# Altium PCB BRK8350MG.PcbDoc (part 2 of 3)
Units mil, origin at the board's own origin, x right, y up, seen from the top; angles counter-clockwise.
Board outline 8858.27 x 5511.81 mil, 6 copper layers (L1-TOP, L2-GND, L3-PWR, L4-PWR, L5-GND, L6-BOT), stack 81.526 mil thick; 49 components, 350 nets, 1087 pads, 250 vias.
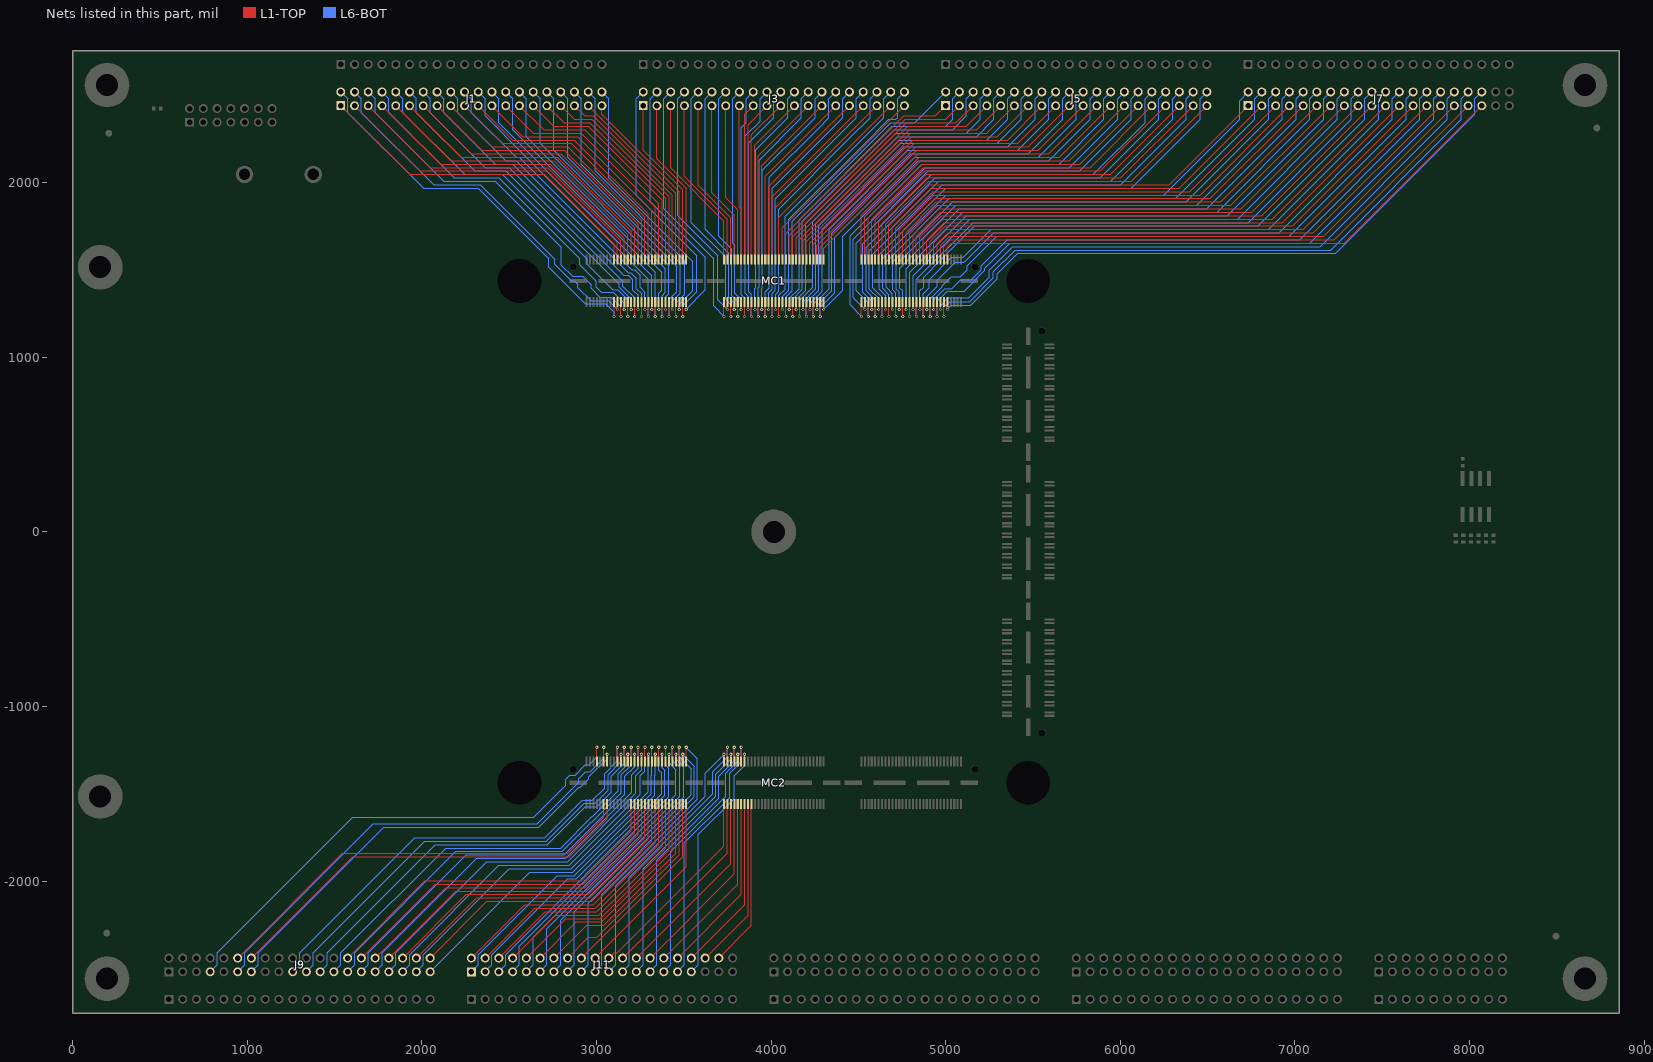
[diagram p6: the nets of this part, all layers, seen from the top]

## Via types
v1: diameter 18, hole 10, L1-TOP to L6-BOT, tented both sides, 250 vias

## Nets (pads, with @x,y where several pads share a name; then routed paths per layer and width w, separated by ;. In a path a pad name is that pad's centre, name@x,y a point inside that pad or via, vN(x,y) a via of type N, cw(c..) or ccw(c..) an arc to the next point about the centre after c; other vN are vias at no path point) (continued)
B44_L7P: J9.7 MC2.7 | length 2919.7
  L1-TOP w5: MC2.7@3001.98,-1313.34 v1(3001.98,-1233.34)
  L6-BOT w5: J9.7@787.4,-2519.69 826.77,-2480.32 826.77,-2411.42 1604.33,-1633.86 2640.14,-1633.86 2824,-1450 2824,-1415.82 2846.82,-1393 2878.98,-1393 2937.03,-1334.95 2958.3,-1334.95 3001.98,-1291.27 v1@3001.98,-1235.34
B44_L8N: J9.14 MC2.14 | length 2452.7
  L1-TOP w5: J9.14@1023.62,-2440.94 1604.33,-1860.24 2844.49,-1860.24 3061.04,-1643.68 MC2.14@3061.04,-1558.65
B44_L8P: J9.12 MC2.12 | length 2506
  L1-TOP w5: J9.12@944.88,-2440.94 1545.28,-1840.55 2834.65,-1840.55 3041.35,-1633.84 MC2.12@3041.35,-1558.65
B44_L9N: J9.13 MC2.13 | length 2655.6
  L1-TOP w5: MC2.13@3061.04,-1313.34 v1(3061.04,-1273.34)
  L6-BOT w5: J9.13@1023.62,-2519.69 1062.99,-2480.32 1062.99,-2411.42 1781.65,-1692.76 2668.42,-1692.76 2898.17,-1463 2908.21,-1463 2956.18,-1415.03 2956.18,-1403.3 3061.04,-1298.44 v1(3061.04,-1273.34)
B44_L9P: J9.11 MC2.11 | length 2796.8
  L1-TOP w5: MC2.11@3041.35,-1313.34 v1(3041.35,-1233.34)
  L6-BOT w5: J9.11@944.88,-2519.69 984.25,-2480.32 984.25,-2411.42 1722.44,-1673.23 2660.35,-1673.23 2899,-1434.57 2899,-1415 2939.97,-1374.03 2964.99,-1374.03 3041.35,-1297.67 v1@3041.35,-1235.34
B44_L10N: J9.21 MC2.21 | length 2474.4
  L1-TOP w5: MC2.21@3139.78,-1313.34 v1(3139.78,-1273.34)
  L6-BOT w5: J9.21@1338.58,-2519.69 1377.95,-2480.32 1377.95,-2411.42 2017.72,-1771.65 2712.35,-1771.65 2931,-1553 2994.24,-1553 3066.05,-1481.19 3066.05,-1390.95 3139.78,-1317.22 v1@3139.78,-1275.34
B44_L10P: J9.19 MC2.19 | length 2605.2
  L1-TOP w5: MC2.19@3120.09,-1313.34 v1(3120.09,-1233.34)
  L6-BOT w5: J9.19@1259.84,-2519.69 1299.21,-2480.32 1299.21,-2411.42 1958.66,-1751.97 2703.03,-1751.97 2918,-1537 2976.57,-1537 3046.03,-1467.54 3046.03,-1385.97 3120.09,-1311.91 v1@3120.09,-1235.34
B45_L1N: J11.12 MC2.52 | length 1282.7
  L1-TOP w5: J11.12@2677.17,-2440.94 2883.86,-2234.25 3031.5,-2234.25 3435.06,-1830.69 MC2.52@3435.06,-1558.65
B45_L1P: J11.10 MC2.50 | length 1336
  L1-TOP w5: J11.10@2598.43,-2440.94 2824.8,-2214.57 3021.65,-2214.57 3415.37,-1820.85 MC2.50@3415.37,-1558.65
B45_L2N: J11.4 MC2.44 | length 1495.9
  L1-TOP w5: J11.4@2362.2,-2440.94 2647.64,-2155.51 2992.13,-2155.51 3356.31,-1791.32 MC2.44@3356.31,-1558.65
B45_L2P: J11.2 MC2.42 | length 1549.2
  L1-TOP w5: J11.2@2283.46,-2440.94 2588.58,-2135.83 2982.28,-2135.83 3336.63,-1781.48 MC2.42@3336.63,-1558.65
B45_L3N: J11.38 MC2.78 | length 959.8
  L1-TOP w5: J11.38@3700.79,-2440.94 3887.81,-2253.92 MC2.78@3887.81,-1558.65
B45_L3P: J11.36 MC2.76 | length 984.2
  L1-TOP w5: J11.36@3622.05,-2440.94 3868.13,-2194.87 MC2.76@3868.13,-1558.65
B45_L4N: J11.29 MC2.69 | length 1459.7
  L1-TOP w5: MC2.69@3809.07,-1313.34 v1(3809.07,-1273.34)
  L6-BOT w5: J11.29@3385.83,-2519.69 3425.2,-2480.31 3425.2,-1830.71 3740.61,-1515.29 3740.61,-1382.39 3809.07,-1313.93 v1@3809.07,-1275.34
B45_L4P: J11.27 MC2.67 | length 1564.1
  L1-TOP w5: MC2.67@3789.39,-1313.34 v1(3789.39,-1233.34)
  L6-BOT w5: J11.27@3307.09,-2519.69 3346.46,-2480.31 3346.46,-1879.92 3700,-1526.38 3700,-1399 3789.39,-1309.61 v1@3789.39,-1235.34
B45_L5N: J11.20 MC2.60 | length 1098.4
  L1-TOP w5: J11.20@2992.13,-2440.94 3041.34,-2391.73 3513.8,-1919.28 MC2.60@3513.8,-1558.65
B45_L5P: J11.18 MC2.58 | length 1122.8
  L1-TOP w5: J11.18@2913.39,-2440.94 2982.28,-2372.05 3494.11,-1860.22 MC2.58@3494.11,-1558.65
B45_L6N: J9.40 MC2.40 | length 1759.9
  L1-TOP w5: J9.40@2047.24,-2440.95 2372.05,-2116.14 2972.44,-2116.14 3316.94,-1771.64 MC2.40@3316.94,-1558.65
B45_L6P: J9.38 MC2.38 | length 1813.2
  L1-TOP w5: J9.38@1968.5,-2440.95 2312.99,-2096.46 2962.6,-2096.46 3297.26,-1761.8 MC2.38@3297.26,-1558.65
B45_L7N: J11.8 MC2.48 | length 1389.3
  L1-TOP w5: J11.8@2519.68,-2440.94 2765.75,-2194.88 3011.81,-2194.88 3395.69,-1811.01 MC2.48@3395.69,-1558.65
B45_L7P: J11.6 MC2.46 | length 1442.6
  L1-TOP w5: J11.6@2440.94,-2440.94 2706.69,-2175.2 3001.97,-2175.2 3376,-1801.17 MC2.46@3376,-1558.65
B45_L8N: J11.19 MC2.59 | length 1633.6
  L1-TOP w5: MC2.59@3513.8,-1313.34 v1(3513.8,-1233.34)
  L6-BOT w5: J11.19@2992.13,-2519.69 3031.5,-2480.31 3031.5,-2077.5 3578,-1531 3578,-1299.54 v1@3513.8,-1235.34
B45_L8P: J11.17 MC2.57 | length 1580.6
  L1-TOP w5: MC2.57@3494.11,-1313.34 v1(3494.11,-1273.34)
  L6-BOT w5: J11.17@2913.39,-2519.69 2952.76,-2480.31 2952.76,-2125.98 3561.31,-1517.43 3561.31,-1342.54 v1@3494.11,-1275.34
B45_L9N: J11.24 MC2.64 | length 1131
  L1-TOP w5: J11.24@3149.61,-2440.94 3750.02,-1840.54 MC2.64@3750.02,-1558.65
B45_L9P: J11.22 MC2.62 | length 1167
  L1-TOP w5: J11.22@3070.87,-2440.94 3100.39,-2411.42 3120.08,-2411.42 3730.33,-1801.17 MC2.62@3730.33,-1558.65
B45_L10N: J11.15 MC2.55 | length 1687.1
  L1-TOP w5: MC2.55@3474.43,-1313.34 v1(3474.43,-1233.34)
  L6-BOT w5: J11.15@2834.65,-2519.69 2874.02,-2480.32 2874.02,-2175.2 3544.18,-1505.03 3544.18,-1357.18 3474.43,-1287.43 v1@3474.43,-1235.34
B45_L10P: J11.13 MC2.53 | length 1612.1
  L1-TOP w5: MC2.53@3454.74,-1313.34 v1(3454.74,-1273.34)
  L6-BOT w5: J11.13@2755.91,-2519.69 2795.28,-2480.31 2795.28,-2224.41 3501,-1518.68 3501,-1345 3454.74,-1298.74 v1@3454.74,-1275.34
B45_L11N: J11.33 MC2.73 | length 1410.7
  L1-TOP w5: MC2.73@3848.44,-1313.34 v1(3848.44,-1273.34)
  L6-BOT w5: J11.33@3543.31,-2519.69 3582.68,-2480.31 3582.68,-1732.28 3787.72,-1527.24 3787.72,-1396.28 3848.44,-1335.56 v1@3848.44,-1275.34
B45_L11P: J11.31 MC2.71 | length 1515.2
  L1-TOP w5: MC2.71@3828.76,-1313.34 v1(3828.76,-1233.34)
  L6-BOT w5: J11.31@3464.57,-2519.69 3503.94,-2480.31 3503.94,-1781.5 3763.57,-1521.86 3763.57,-1381.43 3828.76,-1316.24 v1@3828.76,-1235.34
B45_L12N: J11.7 MC2.47 | length 1741.5
  L1-TOP w5: MC2.47@3395.69,-1313.34 v1(3395.69,-1233.34)
  L6-BOT w5: J11.7@2519.68,-2519.69 2559.06,-2480.32 2559.06,-2372.05 3413,-1518.1 3413,-1353 3395.69,-1335.69 v1@3395.69,-1235.34
B45_L12P: J11.5 MC2.45 | length 1684.9
  L1-TOP w5: MC2.45@3376,-1313.34 v1(3376,-1273.34)
  L6-BOT w5: J11.5@2440.94,-2519.69 2480.32,-2480.31 2480.32,-2421.26 3392,-1509.57 3392,-1366 3376,-1350 v1@3376,-1275.34
B45_L13N: J11.34 MC2.74 | length 1008.7
  L1-TOP w5: J11.34@3543.31,-2440.94 3848.44,-2135.81 MC2.74@3848.44,-1558.65
B45_L13P: J11.32 MC2.72 | length 1033.2
  L1-TOP w5: J11.32@3464.57,-2440.94 3828.76,-2076.76 MC2.72@3828.76,-1558.65
B45_L14N: J11.30 MC2.70 | length 1057.6
  L1-TOP w5: J11.30@3385.83,-2440.94 3809.07,-2017.7 MC2.70@3809.07,-1558.65
B45_L14P: J11.28 MC2.68 | length 1082.1
  L1-TOP w5: J11.28@3307.09,-2440.94 3789.39,-1958.65 MC2.68@3789.39,-1558.65
B45_L15N: J9.34 MC2.34 | length 1919.8
  L1-TOP w5: J9.34@1811.02,-2440.95 2194.88,-2057.09 2942.91,-2057.09 3257.89,-1742.11 MC2.34@3257.89,-1558.65
B45_L15P: J9.32 MC2.32 | length 1973.1
  L1-TOP w5: J9.32@1732.28,-2440.95 2135.83,-2037.4 2933.07,-2037.4 3238.2,-1732.27 MC2.32@3238.2,-1558.65
B45_L16N: J11.23 MC2.63 | length 1613
  L1-TOP w5: MC2.63@3750.02,-1313.34 v1(3750.02,-1233.34)
  L6-BOT w5: J11.23@3149.61,-2519.69 3188.98,-2480.31 3188.98,-1978.35 3666,-1501.32 3666,-1374 3750.02,-1289.98 v1@3750.02,-1235.34
B45_L16P: J11.21 MC2.61 | length 1557.5
  L1-TOP w5: MC2.61@3730.33,-1313.34 v1(3730.33,-1273.34)
  L6-BOT w5: J11.21@3070.87,-2519.69 3110.24,-2480.31 3110.24,-2027.56 3622.27,-1515.52 3622.27,-1383.4 v1@3730.33,-1275.34
B45_L17N: J11.16 MC2.56 | length 1176.1
  L1-TOP w5: J11.16@2834.65,-2440.94 2952.76,-2322.83 3001.97,-2322.83 3474.43,-1850.38 MC2.56@3474.43,-1558.65
B45_L17P: J11.14 MC2.54 | length 1229.4
  L1-TOP w5: J11.14@2755.91,-2440.94 2942.91,-2253.94 3041.34,-2253.94 3454.74,-1840.54 MC2.54@3454.74,-1558.65
B45_L18N: J9.33 MC2.33 | length 2154.6
  L1-TOP w5: MC2.33@3257.89,-1313.34 v1(3257.89,-1273.34)
  L6-BOT w5: J9.33@1811.02,-2519.69 1850.39,-2480.32 1850.39,-2411.42 2372.05,-1889.76 2834.65,-1889.76 3226,-1498.41 3226,-1395.78 3257.89,-1363.89 v1@3257.89,-1275.34
B45_L18P: J9.31 MC2.31 | length 2287.9
  L1-TOP w5: MC2.31@3238.2,-1313.34 v1(3238.2,-1233.34)
  L6-BOT w5: J9.31@1732.28,-2519.69 1771.65,-2480.32 1771.65,-2411.42 2312.99,-1870.08 2824.8,-1870.08 3202.94,-1491.94 3202.94,-1390.03 3238.2,-1354.77 v1@3238.2,-1235.34
B45_L19N: J11.11 MC2.51 | length 1713
  L1-TOP w5: MC2.51@3435.06,-1313.34 v1(3435.06,-1233.34)
  L6-BOT w5: J11.11@2677.17,-2519.69 2716.54,-2480.32 2716.54,-2273.62 3477,-1513.16 3477,-1349 3435.06,-1307.06 v1@3435.06,-1235.34
B45_L19P: J11.9 MC2.49 | length 1655.6
  L1-TOP w5: MC2.49@3415.37,-1313.34 v1(3415.37,-1273.34)
  L6-BOT w5: J11.9@2598.43,-2519.69 2637.8,-2480.31 2637.8,-2322.83 3455,-1505.63 3455,-1362 3415.37,-1322.37 v1@3415.37,-1275.34
B45_L20N: J9.29 MC2.29 | length 2261.2
  L1-TOP w5: MC2.29@3218.52,-1313.34 v1(3218.52,-1273.34)
  L6-BOT w5: J9.29@1653.54,-2519.69 1692.91,-2480.32 1692.91,-2411.42 2253.94,-1850.39 2814.96,-1850.39 3162.31,-1503.04 3162.31,-1400.6 3218.52,-1344.39 v1@3218.52,-1275.34
B45_L20P: J9.27 MC2.27 | length 2394.5
  L1-TOP w5: MC2.27@3198.83,-1313.34 v1(3198.83,-1233.34)
  L6-BOT w5: J9.27@1574.8,-2519.69 1614.17,-2480.32 1614.17,-2411.42 2194.88,-1830.71 2805.12,-1830.71 3142.2,-1493.63 3142.2,-1392.43 3198.83,-1335.79 v1@3198.83,-1235.34
B45_L21N: J11.3 MC2.43 | length 1819.1
  L1-TOP w5: MC2.43@3356.32,-1313.34 v1(3356.32,-1233.34)
  L6-BOT w5: J11.3@2362.2,-2519.69 2401.57,-2480.32 2401.57,-2421.26 2834.65,-1988.19 2883.86,-1988.19 3373.39,-1498.66 3373.39,-1381.07 3356.32,-1364 v1@3356.32,-1235.34
B45_L21P: J11.1 MC2.41 | length 1778.2
  L1-TOP w5: MC2.41@3336.63,-1313.34 v1(3336.63,-1273.34)
  L6-BOT w5: J11.1@2283.46,-2519.69 2322.83,-2480.32 2322.83,-2421.26 2775.59,-1968.5 2874.02,-1968.5 3333.87,-1508.65 3333.87,-1395.05 3336.63,-1392.29 v1@3336.63,-1275.34
B45_L22N: J9.25 MC2.25 | length 2368.1
  L1-TOP w5: MC2.25@3179.15,-1313.34 v1(3179.15,-1273.34)
  L6-BOT w5: J9.25@1496.06,-2519.69 1535.43,-2480.32 1535.43,-2411.42 2135.83,-1811.02 2795.28,-1811.02 2977.15,-1629.15 2977.65,-1629.15 2993.18,-1613.62 2993.18,-1613.12 3123.64,-1482.66 3123.64,-1385.89 3179.15,-1330.39 v1@3179.15,-1275.34
B45_L22P: J9.23 MC2.23 | length 2501.1
  L1-TOP w5: MC2.23@3159.46,-1313.34 v1(3159.46,-1233.34)
  L6-BOT w5: J9.23@1417.32,-2519.69 1456.69,-2480.32 1456.69,-2411.42 2076.77,-1791.34 2719.34,-1791.34 2935.68,-1575 3001.77,-1575 3084.1,-1492.67 3084.1,-1399.67 3159.46,-1324.3 v1@3159.46,-1235.34
B45_L23N: J9.30 MC2.30 | length 2026.4
  L1-TOP w5: J9.30@1653.54,-2440.95 2076.77,-2017.72 2923.23,-2017.72 3218.52,-1722.43 MC2.30@3218.52,-1558.65
B45_L23P: J9.28 MC2.28 | length 2079.7
  L1-TOP w5: J9.28@1574.8,-2440.95 2017.72,-1998.03 2913.39,-1998.03 3198.83,-1712.58 MC2.28@3198.83,-1558.65
B45_L24N: J9.39 MC2.39 | length 2034.4
  L1-TOP w5: MC2.39@3316.94,-1313.34 v1(3316.94,-1233.34)
  L6-BOT w5: J9.39@2047.24,-2519.69 2618.11,-1948.82 2864.17,-1948.82 3314,-1498.99 3314,-1397 3316.94,-1394.06 v1@3316.94,-1235.34
B45_L24P: J9.37 MC2.37 | length 2042.3
  L1-TOP w5: MC2.37@3297.26,-1313.34 v1(3297.26,-1273.34)
  L6-BOT w5: J9.37@1968.5,-2519.69 2007.87,-2480.32 2007.87,-2421.26 2500,-1929.13 2854.33,-1929.13 3295.22,-1488.25 3295.22,-1397.04 3297.26,-1395 v1@3297.26,-1275.34
B45_T0U_N12: J9.36 MC2.36 | length 1866.5
  L1-TOP w5: J9.36@1889.76,-2440.95 2253.94,-2076.77 2952.76,-2076.77 3277.57,-1751.95 MC2.36@3277.57,-1558.65
B45_T1U_N12: J9.35 MC2.35 | length 2175.6
  L1-TOP w5: MC2.35@3277.57,-1313.34 v1(3277.57,-1233.34)
  L6-BOT w5: J9.35@1889.76,-2519.69 1929.13,-2480.32 1929.13,-2421.26 2440.94,-1909.45 2844.49,-1909.45 3251,-1502.94 3251,-1396.3 3277.57,-1369.72 v1@3277.57,-1235.34
B45_T2U_N12: J11.26 MC2.66 | length 1106.5
  L1-TOP w5: J11.26@3228.35,-2440.94 3769.7,-1899.59 MC2.66@3769.7,-1558.65
B45_T3U_N12: J11.25 MC2.65 | length 1508.6
  L1-TOP w5: MC2.65@3769.7,-1313.34 v1(3769.7,-1273.34)
  L6-BOT w5: J11.25@3228.35,-2519.69 3267.72,-2480.32 3267.72,-1929.13 3683,-1513.85 3683,-1388 3769.7,-1301.3 v1@3769.7,-1275.34
B46_L1N: J7.5 MC1.141 | length 2646
  L1-TOP w5: MC1.141@4714.58,1558.68 4714.58,1738.6 4924.8,1948.82 6397.64,1948.82 J7.5@6889.76,2440.94
B46_L1P: J7.3 MC1.139 | length 2591.4
  L1-TOP w5: MC1.139@4694.9,1558.68 4694.9,1746.08 4917.32,1968.5 6338.58,1968.5 J7.3@6811.02,2440.94
B46_L2N: J7.30 MC1.166 | length 3622.7
  L1-TOP w5: v1(4950.8,1233.37) MC1.166@4950.8,1313.37
  L6-BOT w5: v1@4950.8,1235.37 4950.8,1321.78 5008.02,1379 5105.53,1379 5224.89,1498.37 5224.89,1510.48 5367.96,1653.54 7086.61,1653.54 7795.28,2362.2 7795.28,2480.31 J7.30@7834.65,2519.69
B46_L2P: J7.28 MC1.164 | length 3493
  L1-TOP w5: v1(4931.12,1273.37) MC1.164@4931.12,1313.37
  L6-BOT w5: v1@4931.12,1275.37 4931.12,1328.12 4995,1392 5034.03,1392 5086.03,1444 5146.05,1444 5204,1501.95 5204,1523.58 5353.64,1673.23 7027.56,1673.23 7716.54,2362.2 7716.54,2480.31 J7.28@7755.91,2519.69
B46_L3N: J5.36 MC1.132 | length 2618.8
  L1-TOP w5: v1(4616.16,1273.37) MC1.132@4616.16,1313.37
  L6-BOT w5: v1@4616.16,1275.37 4616.16,1336.67 4562.49,1390.33 4562.49,1609.74 4960.63,2007.87 5944.88,2007.87 6299.21,2362.2 6299.21,2480.32 J5.36@6338.58,2519.69
B46_L3P: J5.34 MC1.130 | length 2650.3
  L1-TOP w5: v1(4596.47,1233.37) MC1.130@4596.47,1313.37
  L6-BOT w5: v1@4596.47,1235.37 4596.47,1327.86 4544,1380.33 4544,1630.61 4940.94,2027.56 5885.83,2027.56 6220.47,2362.2 6220.47,2480.31 J5.34@6259.84,2519.69
B46_L4N: J7.26 MC1.162 | length 3522.5
  L1-TOP w5: v1(4911.43,1233.37) MC1.162@4911.43,1313.37
  L6-BOT w5: v1@4911.43,1235.37 4911.43,1336.43 4979.48,1404.48 4979.48,1410.52 5030.97,1462 5084,1462 5124,1502 5124,1523.94 5292.97,1692.91 6968.5,1692.91 7637.8,2362.2 7637.8,2480.31 J7.26@7677.17,2519.69
B46_L4P: J7.24 MC1.160 | length 3393
  L1-TOP w5: v1(4891.75,1273.37) MC1.160@4891.75,1313.37
  L6-BOT w5: v1@4891.75,1275.37 4891.75,1346.77 4952,1407.02 4952,1441 5055,1544 5106.97,1544 5275.57,1712.6 6909.45,1712.6 7559.06,2362.2 7559.06,2480.31 J7.24@7598.43,2519.69
B46_L5N: J7.13 MC1.149 | length 2864.7
  L1-TOP w5: MC1.149@4793.32,1558.68 4793.32,1708.68 4954.72,1870.08 6633.86,1870.08 J7.13@7204.72,2440.94
B46_L5P: J7.11 MC1.147 | length 2810
  L1-TOP w5: MC1.147@4773.64,1558.68 4773.64,1716.16 4947.24,1889.76 6574.8,1889.76 J7.11@7125.98,2440.94
B46_L6N: J7.18 MC1.154 | length 3334.6
  L1-TOP w5: v1(4832.69,1233.37) MC1.154@4832.69,1313.37
  L6-BOT w5: v1@4832.69,1235.37 4832.69,1446.87 5157.48,1771.65 6732.28,1771.65 7322.83,2362.2 7322.83,2480.31 J7.18@7362.2,2519.69
B46_L6P: J7.16 MC1.152 | length 3207
  L1-TOP w5: v1(4813.01,1273.37) MC1.152@4813.01,1313.37
  L6-BOT w5: v1@4813.01,1275.37 4813.01,1466.55 5137.8,1791.34 6673.23,1791.34 7244.09,2362.2 7244.09,2480.31 J7.16@7283.46,2519.69
B46_L7N: J5.40 MC1.136 | length 2698.8
  L1-TOP w5: v1(4655.53,1273.37) MC1.136@4655.53,1313.37
  L6-BOT w5: v1@4655.53,1275.37 4655.53,1353.47 4620,1389 4620,1588.5 5000,1968.5 6062.99,1968.5 6456.69,2362.2 6456.69,2480.31 J5.40@6496.06,2519.69
B46_L7P: J5.38 MC1.134 | length 2747.3
  L1-TOP w5: v1(4635.84,1233.37) MC1.134@4635.84,1313.37
  L6-BOT w5: v1@4635.84,1235.37 4635.84,1344.67 4580.98,1399.52 4580.98,1588.86 4980.32,1988.19 6003.94,1988.19 6377.95,2362.2 6377.95,2480.32 J5.38@6417.32,2519.69
B46_L8N: J7.25 MC1.161 | length 3192.8
  L1-TOP w5: MC1.161@4911.43,1558.68 4911.43,1663.8 4999.61,1751.97 6988.19,1751.97 J7.25@7677.17,2440.94
B46_L8P: J7.23 MC1.159 | length 3138.1
  L1-TOP w5: MC1.159@4891.75,1558.68 4891.75,1671.28 4992.13,1771.65 6929.13,1771.65 J7.23@7598.43,2440.94
B46_L9N: J5.32 MC1.128 | length 2533.6
  L1-TOP w5: v1(4576.79,1273.37) MC1.128@4576.79,1313.37
  L6-BOT w5: v1@4576.79,1275.37 4576.79,1320.21 4525.19,1371.81 4525.19,1651.18 4921.26,2047.24 5846.46,2047.24 6141.73,2342.52 6141.73,2480.32 J5.32@6181.1,2519.69
B46_L9P: J5.30 MC1.126 | length 2569
  L1-TOP w5: v1(4557.1,1233.37) MC1.126@4557.1,1313.37
  L6-BOT w5: v1@4557.1,1235.37 4557.1,1310.9 4488,1380 4488,1653.35 4901.57,2066.93 5767.72,2066.93 6062.99,2362.2 6062.99,2480.31 J5.30@6102.36,2519.69
B46_L10N: J7.34 MC1.170 | length 3732.4
  L1-TOP w5: v1(4990.17,1233.37) MC1.170@4990.17,1313.37
  L6-BOT w5: v1@4990.17,1235.37 4990.17,1285.17 5023,1318 5136.58,1318 5273.76,1455.18 5273.76,1489.5 5398.44,1614.17 7204.72,1614.17 7952.76,2362.2 7952.76,2480.31 J7.34@7992.13,2519.69
B46_L10P: J7.32 MC1.168 | length 3601.7
  L1-TOP w5: v1(4970.49,1273.37) MC1.168@4970.49,1313.37
  L6-BOT w5: v1@4970.49,1275.37 4970.49,1294.49 5016,1340 5130.8,1340 5248.83,1458.03 5248.83,1497.33 5385.36,1633.86 7145.67,1633.86 7874.02,2362.2 7874.02,2480.31 J7.32@7913.39,2519.69
B46_L11N: J7.6 MC1.142 | length 3063.2
  L1-TOP w5: v1(4714.58,1233.37) MC1.142@4714.58,1313.37
  L6-BOT w5: v1@4714.58,1235.37 4714.58,1370.08 4697.97,1386.69 4697.97,1548.36 5039.37,1889.76 6377.95,1889.76 6850.39,2362.2 6850.39,2480.32 J7.6@6889.76,2519.69
B46_L11P: J7.4 MC1.140 | length 2952
  L1-TOP w5: v1(4694.9,1273.37) MC1.140@4694.9,1313.37
  L6-BOT w5: v1@4694.9,1275.37 4694.9,1364.1 4658.56,1400.44 4658.56,1548.32 5019.69,1909.45 6318.9,1909.45 6771.65,2362.2 6771.65,2480.31 J7.4@6811.02,2519.69
B46_L12N: J7.10 MC1.146 | length 3157.8
  L1-TOP w5: v1(4753.95,1233.37) MC1.146@4753.95,1313.37
  L6-BOT w5: v1@4753.95,1235.37 4753.95,1380.3 4737.9,1396.35 4737.9,1509.55 5078.74,1850.39 6496.06,1850.39 7007.87,2362.2 7007.87,2480.32 J7.10@7047.24,2519.69
B46_L12P: J7.8 MC1.144 | length 3030.3
  L1-TOP w5: v1(4734.27,1273.37) MC1.144@4734.27,1313.37
  L6-BOT w5: v1@4734.27,1275.37 4734.27,1373.11 4718.17,1389.2 4718.17,1529.2 5059.06,1870.08 6437.01,1870.08 6929.13,2362.2 6929.13,2480.32 J7.8@6968.5,2519.69
B46_L13N: J7.22 MC1.158 | length 3432.3
  L1-TOP w5: v1(4872.06,1233.37) MC1.158@4872.06,1313.37
  L6-BOT w5: v1@4872.06,1235.37 4872.06,1364.73 4905,1397.67 4905,1445 5033,1573 5101.97,1573 5261.25,1732.28 6850.39,1732.28 7480.31,2362.2 7480.31,2480.32 J7.22@7519.69,2519.69
B46_L13P: J7.20 MC1.156 | length 3308.7
  L1-TOP w5: v1(4852.38,1273.37) MC1.156@4852.38,1313.37
  L6-BOT w5: v1@4852.38,1275.37 4852.38,1380.01 4873.54,1401.18 4873.54,1459.54 4984.63,1570.63 4984.63,1570.77 5165.83,1751.97 6791.34,1751.97 7401.57,2362.2 7401.57,2480.31 J7.20@7440.94,2519.69
B46_L14N: J7.17 MC1.153 | length 2974.1
  L1-TOP w5: MC1.153@4832.69,1558.68 4832.69,1693.72 4969.69,1830.71 6751.97,1830.71 J7.17@7362.2,2440.94
B46_L14P: J7.15 MC1.151 | length 2919.4
  L1-TOP w5: MC1.151@4813.01,1558.68 4813.01,1701.2 4962.2,1850.39 6692.91,1850.39 J7.15@7283.46,2440.94
B46_L15N: J7.29 MC1.165 | length 3302.1
  L1-TOP w5: MC1.165@4950.8,1558.68 4950.8,1648.83 5014.57,1712.6 7106.3,1712.6 J7.29@7834.65,2440.94
B46_L15P: J7.27 MC1.163 | length 3247.4
  L1-TOP w5: MC1.163@4931.12,1558.68 4931.12,1656.31 5007.09,1732.28 7047.24,1732.28 J7.27@7755.91,2440.94
B46_L16N: J7.33 MC1.169 | length 3411.4
  L1-TOP w5: MC1.169@4990.17,1558.68 4990.17,1633.86 5029.54,1673.23 7224.41,1673.23 J7.33@7992.13,2440.94
B46_L16P: J7.31 MC1.167 | length 3356.6
  L1-TOP w5: MC1.167@4970.49,1558.68 4970.49,1641.08 5022.32,1692.91 7165.35,1692.91 J7.31@7913.39,2440.94
B46_L17N: J7.21 MC1.157 | length 3083.4
  L1-TOP w5: MC1.157@4872.06,1558.68 4872.06,1678.76 4984.65,1791.34 6870.08,1791.34 J7.21@7519.69,2440.94
B46_L17P: J7.19 MC1.155 | length 3028.7
  L1-TOP w5: MC1.155@4852.38,1558.68 4852.38,1686.24 4977.17,1811.02 6811.02,1811.02 J7.19@7440.94,2440.94
B46_L18N: J7.14 MC1.150 | length 3239.5
  L1-TOP w5: v1(4793.32,1233.37) MC1.150@4793.32,1313.37
  L6-BOT w5: v1@4793.32,1235.37 4793.32,1486.24 5118.11,1811.02 6614.17,1811.02 7165.35,2362.2 7165.35,2480.32 J7.14@7204.72,2519.69
B46_L18P: J7.12 MC1.148 | length 3112
  L1-TOP w5: v1(4773.64,1273.37) MC1.148@4773.64,1313.37
  L6-BOT w5: v1@4773.64,1275.37 4773.64,1505.92 5098.43,1830.71 6555.12,1830.71 7086.61,2362.2 7086.61,2480.32 J7.12@7125.98,2519.69
B46_L19N: J5.39 MC1.135 | length 2324.5
  L1-TOP w5: MC1.135@4655.53,1558.68 4655.53,1761.04 4902.36,2007.87 6062.99,2007.87 J5.39@6496.06,2440.94
B46_L19P: J5.37 MC1.133 | length 2269.9
  L1-TOP w5: MC1.133@4635.84,1558.68 4635.84,1768.52 4894.88,2027.56 6003.94,2027.56 J5.37@6417.32,2440.94
B46_L20N: J7.9 MC1.145 | length 2755.4
  L1-TOP w5: MC1.145@4753.95,1558.68 4753.95,1723.64 4939.76,1909.45 6515.75,1909.45 J7.9@7047.24,2440.94
B46_L20P: J7.7 MC1.143 | length 2700.7
  L1-TOP w5: MC1.143@4734.27,1558.68 4734.27,1731.12 4932.28,1929.13 6456.69,1929.13 J7.7@6968.5,2440.94
B46_L21N: J5.27 MC1.123 | length 1996.5
  L1-TOP w5: MC1.123@4537.42,1558.68 4537.42,1805.92 4857.48,2125.98 5708.66,2125.98 J5.27@6023.62,2440.94
B46_L21P: J5.25 MC1.121 | length 1941.8
  L1-TOP w5: MC1.121@4517.73,1558.68 4517.73,1813.4 4850,2145.67 5649.61,2145.67 J5.25@5944.88,2440.94
B46_L22N: J5.35 MC1.131 | length 2215.2
  L1-TOP w5: MC1.131@4616.16,1558.68 4616.16,1776 4887.4,2047.24 5944.88,2047.24 J5.35@6338.58,2440.94
B46_L22P: J5.33 MC1.129 | length 2160.5
  L1-TOP w5: MC1.129@4596.47,1558.68 4596.47,1783.48 4879.92,2066.93 5885.83,2066.93 J5.33@6259.84,2440.94
B46_L23N: J5.28 MC1.124 | length 2439.6
  L1-TOP w5: v1(4537.42,1273.37) MC1.124@4537.42,1313.37
  L6-BOT w5: v1@4537.42,1275.37 4470.62,1342.16 4470.62,1675.35 4881.89,2086.61 5708.66,2086.61 5984.25,2362.2 5984.25,2480.32 J5.28@6023.62,2519.69
B46_L23P: J5.26 MC1.122 | length 2470.5
  L1-TOP w5: v1(4517.73,1233.37) MC1.122@4517.73,1313.37
  L6-BOT w5: v1@4517.73,1235.37 4452.82,1300.29 4452.82,1696.91 4862.2,2106.3 5649.61,2106.3 5905.51,2362.2 5905.51,2480.31 J5.26@5944.88,2519.69
B46_L24N: J5.31 MC1.127 | length 2105.8
  L1-TOP w5: MC1.127@4576.79,1558.68 4576.79,1790.96 4872.44,2086.61 5826.77,2086.61 J5.31@6181.1,2440.94
B46_L24P: J5.29 MC1.125 | length 2051.2
  L1-TOP w5: MC1.125@4557.1,1558.68 4557.1,1798.44 4864.96,2106.3 5767.72,2106.3 J5.29@6102.36,2440.94
B46_T0U_N12: J7.35 MC1.171 | length 3468.6
  L1-TOP w5: MC1.171@5009.86,1558.68 5009.86,1630.66 5032.74,1653.54 7283.46,1653.54 J7.35@8070.87,2440.94
B46_T1U_N12: J7.1 MC1.137 | length 2536.7
  L1-TOP w5: MC1.137@4675.21,1558.68 4675.21,1753.56 4909.84,1988.19 6279.53,1988.19 J7.1@6732.28,2440.94
B46_T2U_N12: J7.36 MC1.172 | length 3684.2
  L1-TOP w5: v1(5009.86,1273.37) MC1.172@5009.86,1313.37
  L6-BOT w5: v1@5009.86,1275.37 5032.49,1298 5144.85,1298 5296.74,1449.89 5296.74,1477.84 5413.39,1594.49 7233.49,1594.49 8031.5,2392.5 8031.5,2480.32 J7.36@8070.87,2519.69
B46_T3U_N12: J7.2 MC1.138 | length 2978.4
  L1-TOP w5: v1(4675.21,1233.37) MC1.138@4675.21,1313.37
  L6-BOT w5: v1@4675.21,1235.37 4675.21,1359.19 4639.26,1395.14 4639.26,1568.39 5000,1929.13 6250,1929.13 6683.07,2362.2 6683.07,2470.47 J7.2@6732.28,2519.69
B47_L1N: J5.13 MC1.109 | length 1695.3
  L1-TOP w5: MC1.109@4202.77,1558.68 4202.77,1661.43 4483.82,1942.48 4805.12,2263.78 5295.28,2263.78 J5.13@5472.44,2440.94
B47_L1P: J5.11 MC1.107 | length 1640.6
  L1-TOP w5: MC1.107@4183.09,1558.68 4183.09,1668.91 4797.64,2283.46 5236.22,2283.46 J5.11@5393.7,2440.94
B47_L2N: J5.10 MC1.106 | length 2106.5
  L1-TOP w5: v1(4163.4,1233.37) MC1.106@4163.4,1313.37
  L6-BOT w5: v1@4163.4,1235.37 4163.4,1325.4 4238.03,1400.03 4238.03,1777.4 4724.41,2263.78 5177.17,2263.78 5275.59,2362.2 5275.59,2480.32 J5.10@5314.96,2519.69
B47_L2P: J5.8 MC1.104 | length 1973.2
  L1-TOP w5: v1(4143.72,1273.37) MC1.104@4143.72,1313.37
  L6-BOT w5: v1@4143.72,1275.37 4143.72,1328.72 4199.67,1384.67 4199.67,1768.57 4714.57,2283.46 5118.11,2283.46 5196.85,2362.2 5196.85,2480.32 J5.8@5236.22,2519.69
B47_L3N: J5.21 MC1.117 | length 1914
  L1-TOP w5: MC1.117@4281.51,1558.68 4281.51,1631.51 4835.04,2185.04 5531.5,2185.04 J5.21@5787.4,2440.94
B47_L3P: J5.19 MC1.115 | length 1859.3
  L1-TOP w5: MC1.115@4261.83,1558.68 4261.83,1638.99 4827.56,2204.72 5472.44,2204.72 J5.19@5708.66,2440.94
B47_L4N: J3.23 MC1.79 | length 976
  L1-TOP w5: MC1.79@3907.5,1558.68 3907.5,2214.58 J3.23@4133.86,2440.94
B47_L4P: J3.21 MC1.77 | length 951.6
  L1-TOP w5: MC1.77@3887.81,1558.68 3887.81,2273.64 J3.21@4055.12,2440.94
B47_L5N: J3.16 MC1.72 | length 1321
  L1-TOP w5: v1(3828.76,1273.37) MC1.72@3828.76,1313.37
  L6-BOT w5: J3.16@3818.9,2519.69 3779.53,2480.31 3779.53,1653.56 3792.62,1640.47 3792.62,1367.5 3828.76,1331.36 v1@3828.76,1275.37
B47_L5P: J3.14 MC1.70 | length 1425.5
  L1-TOP w5: v1(3809.07,1233.37) MC1.70@3809.07,1313.37
  L6-BOT w5: J3.14@3740.16,2519.69 3700.79,2480.32 3700.79,1692.91 3775.51,1618.19 3775.51,1352.49 3809.07,1318.93 v1@3809.07,1235.37
B47_L6N: J3.28 MC1.84 | length 1427
  L1-TOP w5: v1(3946.87,1273.37) MC1.84@3946.87,1313.37
  L6-BOT w5: v1@3946.87,1275.37 3946.87,1393.87 3949.94,1396.94 3949.94,2070.02 4212.6,2332.68 4251.97,2372.05 4251.97,2480.31 J3.28@4291.34,2519.69
B47_L6P: J3.26 MC1.82 | length 1482.5
  L1-TOP w5: v1(3927.18,1233.37) MC1.82@3927.18,1313.37
  L6-BOT w5: v1@3927.18,1235.37 3927.18,1401.18 3930.92,1404.92 3930.92,2129.74 4173.23,2372.05 4173.23,2480.31 J3.26@4212.6,2519.69
B47_L7N: J3.38 MC1.94 | length 1629.3
  L1-TOP w5: v1(4045.29,1233.37) MC1.94@4045.29,1313.37
  L6-BOT w5: v1@4045.29,1235.37 4045.29,1354.29 4080.76,1389.76 4080.76,1807.13 4645.67,2372.05 4645.67,2480.31 J3.38@4685.04,2519.69
B47_L7P: J3.36 MC1.92 | length 1524.8
  L1-TOP w5: v1(4025.61,1273.37) MC1.92@4025.61,1313.37
  L6-BOT w5: v1@4025.61,1275.37 4025.61,1359.79 4042.73,1376.92 4042.73,1847.85 4448.82,2253.94 4566.93,2372.05 4566.93,2480.31 J3.36@4606.3,2519.69
B47_L8N: J5.17 MC1.113 | length 1804.7
  L1-TOP w5: MC1.113@4242.14,1558.68 4242.14,1646.47 4820.08,2224.41 5413.39,2224.41 J5.17@5629.92,2440.94
B47_L8P: J5.15 MC1.111 | length 1750
  L1-TOP w5: MC1.111@4222.46,1558.68 4222.46,1653.95 4812.6,2244.09 5354.33,2244.09 J5.15@5551.18,2440.94
B47_L9N: J3.19 MC1.75 | length 927.1
  L1-TOP w5: MC1.75@3868.13,1558.68 3868.13,2332.69 J3.19@3976.38,2440.94
B47_L9P: J3.17 MC1.73 | length 902.6
  L1-TOP w5: MC1.73@3848.44,1558.68 3848.44,2391.75 J3.17@3897.64,2440.94
B47_L10N: J5.18 MC1.114 | length 2308.2
  L1-TOP w5: v1(4242.14,1233.37) MC1.114@4242.14,1313.37
  L6-BOT w5: v1@4242.14,1235.37 4242.14,1303.14 4332,1393 4332,1733.57 4783.46,2185.04 5413.39,2185.04 5590.55,2362.2 5590.55,2480.32 J5.18@5629.92,2519.69
B47_L10P: J5.16 MC1.112 | length 2180.6
  L1-TOP w5: v1(4222.46,1273.37) MC1.112@4222.46,1313.37
  L6-BOT w5: v1@4222.46,1275.37 4222.46,1306.46 4293.57,1377.57 4293.57,1734.52 4763.78,2204.72 5354.33,2204.72 5511.81,2362.2 5511.81,2480.31 J5.16@5551.18,2519.69
B47_L11N: J5.5 MC1.101 | length 1476.6
  L1-TOP w5: MC1.101@4124.03,1558.68 4124.03,1691.35 4775.2,2342.52 5059.06,2342.52 J5.5@5157.48,2440.94
B47_L11P: J5.3 MC1.99 | length 1421.9
  L1-TOP w5: MC1.99@4104.35,1558.68 4104.35,1698.83 4767.72,2362.2 5000,2362.2 J5.3@5078.74,2440.94
B47_L12N: J5.1 MC1.97 | length 1367.3
  L1-TOP w5: MC1.97@4084.66,1558.68 4084.66,1706.32 4465.83,2087.48 4760.24,2381.89 4940.94,2381.89 J5.1@5000,2440.94
B47_L12P: J3.39 MC1.95 | length 1171.7
  L1-TOP w5: MC1.95@4064.98,1558.68 4064.98,1742.14 J3.39@4763.78,2440.94
B47_L13N: J5.9 MC1.105 | length 1586
  L1-TOP w5: MC1.105@4163.4,1558.68 4163.4,1676.39 4790.16,2303.15 5177.17,2303.15 J5.9@5314.96,2440.94
B47_L13P: J5.7 MC1.103 | length 1531.3
  L1-TOP w5: MC1.103@4143.72,1558.68 4143.72,1683.87 4782.68,2322.83 5118.11,2322.83 J5.7@5236.22,2440.94
B47_L14N: J5.22 MC1.118 | length 2403.2
  L1-TOP w5: v1(4281.51,1233.37) MC1.118@4281.51,1313.37
  L6-BOT w5: v1@4281.51,1235.37 4281.51,1285.51 4365,1369 4365,1687.83 4822.83,2145.67 5531.5,2145.67 5748.03,2362.2 5748.03,2480.32 J5.22@5787.4,2519.69
B47_L14P: J5.20 MC1.116 | length 2275.7
  L1-TOP w5: v1(4261.83,1273.37) MC1.116@4261.83,1313.37
  L6-BOT w5: v1@4261.83,1275.37 4261.83,1294.83 4347.94,1380.94 4347.94,1710.15 4803.15,2165.35 5472.44,2165.35 5669.29,2362.2 5669.29,2480.31 J5.20@5708.66,2519.69
B47_L15N: J3.34 MC1.90 | length 1580.4
  L1-TOP w5: v1(4005.92,1233.37) MC1.90@4005.92,1313.37
  L6-BOT w5: v1@4005.92,1235.37 4005.92,1365.35 4024.22,1383.64 4024.22,1908.08 4389.76,2273.62 4488.19,2372.05 4488.19,2480.31 J3.34@4527.56,2519.69
B47_L15P: J3.32 MC1.88 | length 1475.9
  L1-TOP w5: v1(3986.24,1273.37) MC1.88@3986.24,1313.37
  L6-BOT w5: v1@3986.24,1275.37 3986.24,1369.83 4006.21,1389.8 4006.21,1968.8 4409.45,2372.05 4409.45,2480.31 J3.32@4448.82,2519.69
B47_L16N: J5.6 MC1.102 | length 1988.4
  L1-TOP w5: v1(4124.03,1233.37) MC1.102@4124.03,1313.37
  L6-BOT w5: v1@4124.03,1235.37 4124.03,1333.03 4179.66,1388.66 4179.66,1778.08 4704.72,2303.15 5039.37,2303.15 5118.11,2381.89 5118.11,2480.32 J5.6@5157.48,2519.69
B47_L16P: J5.4 MC1.100 | length 1866.7
  L1-TOP w5: v1(4104.35,1273.37) MC1.100@4104.35,1313.37
  L6-BOT w5: v1@4104.35,1275.37 4104.35,1337.35 4159.98,1392.98 4159.98,1787.93 4694.88,2322.83 5000,2322.83 5039.37,2362.2 5039.37,2480.32 J5.4@5078.74,2519.69
B47_L17N: J3.15 MC1.71 | length 886.4
  L1-TOP w5: J3.15@3818.9,2440.94 3818.9,1859.09 3828.76,1849.24 MC1.71@3828.76,1558.68
B47_L17P: J3.13 MC1.69 | length 910.8
  L1-TOP w5: J3.13@3740.16,2440.94 3740.16,1913.32 3809.07,1844.41 MC1.69@3809.07,1558.68
B47_L18N: J3.29 MC1.85 | length 1049.4
  L1-TOP w5: MC1.85@3966.55,1558.68 3966.55,2037.42 J3.29@4370.08,2440.94
B47_L18P: J3.27 MC1.83 | length 1025
  L1-TOP w5: MC1.83@3946.87,1558.68 3946.87,2096.47 J3.27@4291.34,2440.94
B47_L19N: J3.24 MC1.80 | length 1378.1
  L1-TOP w5: v1(3907.5,1273.37) MC1.80@3907.5,1313.37
  L6-BOT w5: v1@3907.5,1275.37 3907.5,1394.02 3910.85,1397.37 3910.85,2188.41 4094.49,2372.05 4094.49,2480.31 J3.24@4133.86,2519.69
B47_L19P: J3.22 MC1.78 | length 1446.8
  L1-TOP w5: v1(3887.81,1233.37) MC1.78@3887.81,1313.37
  L6-BOT w5: v1@3887.81,1235.37 3887.81,1360.3 3871.91,1376.19 3871.91,2228.21 4015.75,2372.05 4015.75,2480.31 J3.22@4055.12,2519.69
B47_L20N: J5.2 MC1.98 | length 1824.2
  L1-TOP w5: v1(4084.66,1233.37) MC1.98@4084.66,1313.37
  L6-BOT w5: v1@4084.66,1235.37 4084.66,1342.66 4122.29,1380.29 4122.29,1779.77 4685.04,2342.52 4822.83,2342.52 J5.2@5000,2519.69
B47_L20P: J3.40 MC1.96 | length 1596.8
  L1-TOP w5: v1(4064.98,1273.37) MC1.96@4064.98,1313.37
  L6-BOT w5: v1@4064.98,1275.37 4064.98,1346.98 4102.1,1384.1 4102.1,1789.11 4527.56,2214.57 4675.2,2362.2 4714.57,2362.2 4724.41,2372.05 4724.41,2480.31 J3.40@4763.78,2519.69
B47_L21N: J3.37 MC1.93 | length 1147.3
  L1-TOP w5: MC1.93@4045.29,1558.68 4045.29,1801.2 J3.37@4685.04,2440.94
B47_L21P: J3.35 MC1.91 | length 1122.8
  L1-TOP w5: MC1.91@4025.61,1558.68 4025.61,1860.25 J3.35@4606.3,2440.94
B47_L22N: J5.14 MC1.110 | length 2213.1
  L1-TOP w5: v1(4202.77,1233.37) MC1.110@4202.77,1313.37
  L6-BOT w5: v1@4202.77,1235.37 4202.77,1314.77 4273.22,1385.22 4273.22,1753.54 4744.09,2224.41 5295.28,2224.41 5433.07,2362.2 5433.07,2480.32 J5.14@5472.44,2519.69
B47_L22P: J5.12 MC1.108 | length 2079.8
  L1-TOP w5: v1(4183.09,1273.37) MC1.108@4183.09,1313.37
  L6-BOT w5: v1@4183.09,1275.37 4183.09,1319.09 4255.71,1391.71 4255.71,1765.55 4734.25,2244.09 5236.22,2244.09 5354.33,2362.2 5354.33,2480.32 J5.12@5393.7,2519.69
B47_L23N: J3.20 MC1.76 | length 1342.3
  L1-TOP w5: v1(3868.13,1273.37) MC1.76@3868.13,1313.37
  L6-BOT w5: v1@3868.13,1275.37 3868.13,1349.73 3852.29,1365.56 3852.29,2267.65 3937.01,2352.36 3937.01,2480.31 J3.20@3976.38,2519.69
B47_L23P: J3.18 MC1.74 | length 1399.5
  L1-TOP w5: v1(3848.44,1233.37) MC1.74@3848.44,1313.37
  L6-BOT w5: v1@3848.44,1235.37 3848.44,1340.83 3830.56,1358.71 3830.56,2314.81 3858.27,2342.52 3858.27,2480.31 J3.18@3897.64,2519.69
B47_L24N: J3.33 MC1.89 | length 1098.3
  L1-TOP w5: MC1.89@4005.92,1558.68 4005.92,1919.31 4295.09,2208.48 J3.33@4527.56,2440.94
B47_L24P: J3.31 MC1.87 | length 1074.3
  L1-TOP w5: MC1.87@3986.24,1558.68 3986.24,1979.15 4246.57,2239.48 4247.35,2239.48 J3.31@4448.82,2440.94
B47_T0U_N12: J5.24 MC1.120 | length 2370.7
  L1-TOP w5: v1(4301.2,1273.37) MC1.120@4301.2,1313.37
  L6-BOT w5: v1@4301.2,1275.37 4409.45,1383.62 4409.45,1692.91 4842.52,2125.98 5590.55,2125.98 5826.77,2362.2 5826.77,2480.32 J5.24@5866.14,2519.69
B47_T1U_N12: J3.25 MC1.81 | length 1000.5
  L1-TOP w5: MC1.81@3927.18,1558.68 3927.18,2155.53 4115.13,2343.48 J3.25@4212.6,2440.94
B47_T2U_N12: J5.23 MC1.119 | length 1968.7
  L1-TOP w5: MC1.119@4301.2,1558.68 4301.2,1624.03 4842.52,2165.35 5590.55,2165.35 J5.23@5866.14,2440.94
B47_T3U_N12: J3.30 MC1.86 | length 1531.5
  L1-TOP w5: v1(3966.55,1233.37) MC1.86@3966.55,1313.37
  L6-BOT w5: v1@3966.55,1235.37 3966.55,1376.45 3988.86,1398.76 3988.86,2030.2 4271.65,2312.99 4330.71,2372.05 4330.71,2480.31 J3.30@4370.08,2519.69
B48_L1N: J1.3 MC1.19 | length 1929.5
  L1-TOP w5: J1.3@1614.17,2440.94 1988.19,2066.93 2711.07,2066.93 3120.09,1657.91 MC1.19@3120.09,1558.68
B48_L1P: J1.1 MC1.17 | length 1983.1
  L1-TOP w5: J1.1@1535.43,2440.94 1929.13,2047.24 2701.76,2047.24 3100.41,1648.59 MC1.17@3100.41,1558.68
B48_L2N: J1.11 MC1.27 | length 1731.1
  L1-TOP w5: J1.11@1929.13,2440.94 2224.41,2145.67 2775.59,2145.67 3198.83,1722.43 MC1.27@3198.83,1558.68
B48_L2P: J1.9 MC1.25 | length 1778.6
  L1-TOP w5: J1.9@1850.39,2440.94 2165.35,2125.98 2755.91,2125.98 3179.15,1702.74 MC1.25@3179.15,1558.68
B48_L3N: J3.3 MC1.59 | length 951.6
  L1-TOP w5: J3.3@3346.46,2440.94 3346.46,2135.83 3513.8,1968.49 MC1.59@3513.8,1558.68
B48_L3P: J3.1 MC1.57 | length 976
  L1-TOP w5: J3.1@3267.72,2440.94 3267.72,2185.04 3494.11,1958.65 MC1.57@3494.11,1558.68
B48_L4N: J1.40 MC1.56 | length 1531.2
  L1-TOP w5: v1(3474.43,1273.37) MC1.56@3474.43,1313.37
  L6-BOT w5: J1.40@3031.5,2519.69 3070.87,2480.32 3070.87,2027.56 3551,1547.43 3551,1380 3474.43,1303.43 v1@3474.43,1275.37
B48_L4P: J1.38 MC1.54 | length 1613.9
  L1-TOP w5: v1(3454.74,1233.37) MC1.54@3454.74,1313.37
  L6-BOT w5: J1.38@2952.76,2519.69 2992.13,2480.31 2992.13,2066.93 3505,1554.06 3505,1361 3454.74,1310.74 v1@3454.74,1235.37
B48_L5N: J3.12 MC1.68 | length 1369.9
  L1-TOP w5: v1(3789.39,1273.37) MC1.68@3789.39,1313.37
  L6-BOT w5: J3.12@3661.42,2519.69 3622.05,2480.31 3622.05,1732.28 3757.49,1596.84 3757.49,1342.51 3789.39,1310.61 v1@3789.39,1275.37
B48_L5P: J3.10 MC1.66 | length 1474.4
  L1-TOP w5: v1(3769.7,1233.37) MC1.66@3769.7,1313.37
  L6-BOT w5: J3.10@3582.68,2519.69 3543.31,2480.32 3543.31,1771.65 3739,1575.96 3739,1331 3769.7,1300.3 v1@3769.7,1235.37
B48_L6N: J1.27 MC1.43 | length 1350.9
  L1-TOP w5: J1.27@2559.06,2440.94 2696.85,2303.15 2933.07,2303.15 3356.31,1879.91 MC1.43@3356.31,1558.68
B48_L6P: J1.25 MC1.41 | length 1398.4
  L1-TOP w5: J1.25@2480.32,2440.94 2637.8,2283.46 2913.39,2283.46 3336.63,1860.22 MC1.41@3336.63,1558.68
B48_L7N: J1.32 MC1.48 | length 1580.8
  L1-TOP w5: v1(3395.69,1273.37) MC1.48@3395.69,1313.37
  L6-BOT w5: J1.32@2716.54,2519.69 2755.91,2480.31 2755.91,2185.04 3414,1526.94 3414,1364 3395.69,1345.69 v1@3395.69,1275.37
B48_L7P: J1.30 MC1.46 | length 1685.8
  L1-TOP w5: v1(3376,1233.37) MC1.46@3376,1313.37
  L6-BOT w5: J1.30@2637.8,2519.69 2677.17,2480.31 2677.17,2224.41 3395,1506.57 3395,1372 3376,1353 v1@3376,1235.37
B48_L8N: J1.8 MC1.24 | length 2049.2
  L1-TOP w5: v1(3159.46,1273.37) MC1.24@3159.46,1313.37
  L6-BOT w5: J1.8@1771.65,2519.69 1811.02,2480.32 1811.02,2401.57 2185.04,2027.56 2440.94,2027.56 2905,1563.5 2905,1529.25 2998,1436.25 2998,1402 3028.75,1371.25 3097.25,1371.25 3159.46,1309.04 v1@3159.46,1275.37
B48_L8P: J1.6 MC1.22 | length 2208.7
  L1-TOP w5: v1(3139.78,1233.37) MC1.22@3139.78,1313.37
  L6-BOT w5: J1.6@1692.91,2519.69 1732.28,2480.32 1732.28,2401.57 2125.98,2007.87 2421.26,2007.87 2799.07,1630.07 2799.07,1527.93 2863,1464 2922,1464 2970,1416 2970,1395 3020,1345 3084.13,1345 3139.78,1289.35 v1@3139.78,1235.37
B48_L9N: J1.23 MC1.39 | length 1445.9
  L1-TOP w5: J1.23@2401.57,2440.94 2578.74,2263.78 2893.7,2263.78 3316.94,1840.54 MC1.39@3316.94,1558.68
B48_L9P: J1.21 MC1.37 | length 1493.4
  L1-TOP w5: J1.21@2322.83,2440.94 2519.68,2244.09 2874.02,2244.09 3297.26,1820.85 MC1.37@3297.26,1558.68
B48_L10N: J3.4 MC1.60 | length 1477.5
  L1-TOP w5: v1(3513.8,1273.37) MC1.60@3513.8,1313.37
  L6-BOT w5: J3.4@3346.46,2519.69 3307.09,2480.31 3307.09,1889.76 3624,1572.85 3624,1385.57 v1@3513.8,1275.37
B48_L10P: J3.2 MC1.58 | length 1557.7
  L1-TOP w5: v1(3494.11,1233.37) MC1.58@3494.11,1313.37
  L6-BOT w5: J3.2@3267.72,2519.69 3228.35,2480.32 3228.35,1929.13 3575,1582.48 3575,1375 3494.11,1294.11 v1@3494.11,1235.37
B48_L11N: J1.39 MC1.55 | length 1065.7
  L1-TOP w5: J1.39@3031.5,2440.94 3031.5,2391.73 3474.43,1948.8 MC1.55@3474.43,1558.68
B48_L11P: J1.37 MC1.53 | length 1090.2
  L1-TOP w5: J1.37@2952.76,2440.94 3454.74,1938.96 MC1.53@3454.74,1558.68
B48_L12N: J1.19 MC1.35 | length 1541
  L1-TOP w5: J1.19@2244.09,2440.94 2460.63,2224.41 2854.33,2224.41 3277.57,1801.17 MC1.35@3277.57,1558.68
B48_L12P: J1.17 MC1.33 | length 1588.5
  L1-TOP w5: J1.17@2165.35,2440.94 2401.57,2204.72 2834.65,2204.72 3257.89,1781.48 MC1.33@3257.89,1558.68
B48_L13N: J3.11 MC1.67 | length 935.3
  L1-TOP w5: J3.11@3661.42,2440.94 3661.42,1942.06 3789.39,1814.09 MC1.67@3789.39,1558.68
B48_L13P: J3.9 MC1.65 | length 959.7
  L1-TOP w5: J3.9@3582.68,2440.94 3582.68,1985.8 3769.7,1798.78 MC1.65@3769.7,1558.68
B48_L14N: J1.4 MC1.20 | length 2135
  L1-TOP w5: v1(3120.09,1273.37) MC1.20@3120.09,1313.37
  L6-BOT w5: J1.4@1614.17,2519.69 1653.54,2480.32 1653.54,2401.57 2066.93,1988.19 2333.81,1988.19 2760,1562 2760,1533 2855,1438 2873,1438 2894,1417 2894,1399 2968.89,1324.11 3071.35,1324.11 v1@3120.09,1275.37
B48_L14P: J1.2 MC1.18 | length 2264.8
  L1-TOP w5: v1(3100.41,1233.37) MC1.18@3100.41,1313.37
  L6-BOT w5: J1.2@1535.43,2519.69 1574.8,2480.32 1574.8,2401.57 2009.38,1967 2323,1967 2726,1564 2726,1516 2936,1306 3053,1306 3100.41,1258.59 v1@3100.41,1235.37
B48_L15N: J1.15 MC1.31 | length 1636
  L1-TOP w5: J1.15@2086.61,2440.94 2342.52,2185.04 2814.96,2185.04 3238.2,1761.8 MC1.31@3238.2,1558.68
B48_L15P: J1.13 MC1.29 | length 1683.5
  L1-TOP w5: J1.13@2007.87,2440.94 2283.46,2165.35 2795.28,2165.35 3218.52,1742.11 MC1.29@3218.52,1558.68
B48_L16N: J1.36 MC1.52 | length 1553.9
  L1-TOP w5: v1(3435.06,1273.37) MC1.52@3435.06,1313.37
  L6-BOT w5: J1.36@2874.02,2519.69 2913.39,2480.31 2913.39,2106.3 3480,1539.69 3480,1366 3435.06,1321.06 v1@3435.06,1275.37
B48_L16P: J1.34 MC1.50 | length 1657.3
  L1-TOP w5: v1(3415.37,1233.37) MC1.50@3415.37,1313.37
  L6-BOT w5: J1.34@2795.28,2519.69 2834.65,2480.31 2834.65,2145.67 3459,1521.32 3459,1376 3415.37,1332.37 v1@3415.37,1235.37
B48_L17N: J1.31 MC1.47 | length 1250.1
  L1-TOP w5: J1.31@2716.54,2440.94 2814.96,2342.52 2962.6,2342.52 3395.69,1909.43 MC1.47@3395.69,1558.68
B48_L17P: J1.29 MC1.45 | length 1303.4
  L1-TOP w5: J1.29@2637.8,2440.94 2755.91,2322.83 2952.76,2322.83 3376,1899.59 MC1.45@3376,1558.68
B48_L18N: J1.12 MC1.28 | length 1914
  L1-TOP w5: v1(3198.83,1273.37) MC1.28@3198.83,1313.37
  L6-BOT w5: J1.12@1929.13,2519.69 1968.5,2480.32 1968.5,2401.57 2303.15,2066.93 2480.32,2066.93 3130,1417.24 3130,1402 3198.83,1333.17 v1@3198.83,1275.37
B48_L18P: J1.10 MC1.26 | length 2057.3
  L1-TOP w5: v1(3179.15,1233.37) MC1.26@3179.15,1313.37
  L6-BOT w5: J1.10@1850.39,2519.69 1889.76,2480.32 1889.76,2401.57 2244.09,2047.24 2460.63,2047.24 2947.44,1560.44 2947.44,1533.56 3094,1387 3120.87,1387 3179.15,1328.72 v1@3179.15,1235.37
B48_L19N: J1.35 MC1.51 | length 1143.5
  L1-TOP w5: J1.35@2874.02,2440.94 2933.07,2381.89 2982.28,2381.89 3435.06,1929.12 MC1.51@3435.06,1558.68
B48_L19P: J1.33 MC1.49 | length 1196.8
  L1-TOP w5: J1.33@2795.28,2440.94 2874.02,2362.2 2972.44,2362.2 3415.37,1919.28 MC1.49@3415.37,1558.68
B48_L20N: J1.24 MC1.40 | length 1663.5
  L1-TOP w5: v1(3316.94,1273.37) MC1.40@3316.94,1313.37
  L6-BOT w5: J1.24@2401.57,2519.69 2440.94,2480.31 2440.94,2342.52 3051.18,1732.28 3316.94,1466.52 v1@3316.94,1275.37
B48_L20P: J1.22 MC1.38 | length 1767.9
  L1-TOP w5: v1(3297.26,1233.37) MC1.38@3297.26,1313.37
  L6-BOT w5: J1.22@2322.83,2519.69 2362.2,2480.31 2362.2,2381.89 2578.74,2165.35 3031.5,1712.6 3297.26,1446.83 v1@3297.26,1235.37
B48_L21N: J1.7 MC1.23 | length 1826.1
  L1-TOP w5: J1.7@1771.65,2440.94 2106.3,2106.3 2736.22,2106.3 3159.46,1683.06 MC1.23@3159.46,1558.68
B48_L21P: J1.5 MC1.21 | length 1876.5
  L1-TOP w5: J1.5@1692.91,2440.94 2047.24,2086.61 2721.39,2086.61 3139.78,1668.22 MC1.21@3139.78,1558.68
B48_L22N: J1.16 MC1.32 | length 1834.2
  L1-TOP w5: v1(3238.2,1273.37) MC1.32@3238.2,1313.37
  L6-BOT w5: J1.16@2086.61,2519.69 2125.98,2480.31 2125.98,2401.57 2421.26,2106.3 2519.69,2106.3 3155.99,1469.99 3182.01,1469.99 3209,1443 3209,1385.2 3238.2,1356 v1@3238.2,1275.37
B48_L22P: J1.14 MC1.30 | length 1946.5
  L1-TOP w5: v1(3218.52,1233.37) MC1.30@3218.52,1313.37
  L6-BOT w5: J1.14@2007.87,2519.69 2047.24,2480.32 2047.24,2401.57 2362.2,2086.61 2500,2086.61 2952.76,1633.86 3150.31,1436.31 3150.31,1408.07 3218.52,1339.86 v1@3218.52,1235.37
B48_L23N: J1.20 MC1.36 | length 1733.5
  L1-TOP w5: v1(3277.57,1273.37) MC1.36@3277.57,1313.37
  L6-BOT w5: J1.20@2244.09,2519.69 2283.46,2480.31 2283.46,2401.57 2539.37,2145.67 2559.06,2145.67 3202.86,1501.86 3219.14,1501.86 3250,1471 3250,1401 3277.57,1373.43 v1@3277.57,1275.37
B48_L23P: J1.18 MC1.34 | length 1861.2
  L1-TOP w5: v1(3257.89,1233.37) MC1.34@3257.89,1313.37
  L6-BOT w5: J1.18@2165.35,2519.69 2204.72,2480.31 2204.72,2401.57 2480.32,2125.98 2540.16,2125.98 3181.07,1485.07 3196.93,1485.07 3229,1453 3229,1393 3257.89,1364.11 v1@3257.89,1235.37
B48_L24N: J1.28 MC1.44 | length 1629.2
  L1-TOP w5: v1(3356.31,1273.37) MC1.44@3356.31,1313.37
  L6-BOT w5: J1.28@2559.06,2519.69 2598.43,2480.31 2598.43,2263.78 3374,1488.2 3374,1383 3356.31,1365.31 v1@3356.31,1275.37
B48_L24P: J1.26 MC1.42 | length 1719
  L1-TOP w5: v1(3336.63,1233.37) MC1.42@3336.63,1313.37
  L6-BOT w5: J1.26@2480.32,2519.69 2519.68,2480.32 2519.68,2303.15 3070.87,1751.97 3336.63,1486.2 v1@3336.63,1235.37
B48_T0U_N12: J3.8 MC1.64 | length 1418.9
  L1-TOP w5: v1(3750.02,1273.37) MC1.64@3750.02,1313.37
  L6-BOT w5: J3.8@3503.94,2519.69 3464.57,2480.31 3464.57,1811.02 3695,1580.59 3695,1330.39 v1@3750.02,1275.37
B48_T1U_N12: J3.7 MC1.63 | length 984.2
  L1-TOP w5: J3.7@3503.94,2440.94 3503.94,2035.54 3750.02,1789.46 MC1.63@3750.02,1558.68
B48_T2U_N12: J3.6 MC1.62 | length 1523.3
  L1-TOP w5: v1(3730.33,1233.37) MC1.62@3730.33,1313.37
  L6-BOT w5: J3.6@3425.2,2519.69 3385.83,2480.32 3385.83,1850.39 3671,1565.22 3671,1294.7 v1@3730.33,1235.37
B48_T3U_N12: J3.5 MC1.61 | length 1008.7
  L1-TOP w5: J3.5@3425.2,2440.94 3425.2,2084.28 3730.33,1779.15 MC1.61@3730.33,1558.68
